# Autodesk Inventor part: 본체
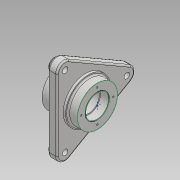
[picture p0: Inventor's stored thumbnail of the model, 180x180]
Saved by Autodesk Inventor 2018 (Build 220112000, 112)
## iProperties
Created: 2023-04
Part Number: 본체
Material: 일반
Document SubType Name: Modeling
Designer: home
Density: 1 g/cm^3
Appearance: 기본값
Author: home
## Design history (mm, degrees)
sketch "스케치1" dims "d0" = 57
  geometry: L1 (-33, 84.87)-(90, 13.856); L2 (90, -13.856)-(-33, -84.87); L3 (-57, -71.014)-(-57, 71.014); A1 r 16 centre (82, 0) between (90, -13.856) and (90, 13.856); A2 r 16 centre (-41, 71.014) between (-33, 84.87) and (-57, 71.014); A3 r 16 centre (-41, -71.014) between (-57, -71.014) and (-33, -84.87); 7 further points
  constraints: 6 end point, 6 point on circle, 6 point on line, 6 tangent, 3 centre point, 2 coincident, 2 equal radius, 1 horizontal alignment, 1 midpoint, 9 other
  dimensions: "d1" = 16 radius of A1 (derived)
extrude "돌출1" new body sketch "스케치1" distance "d2" = 18; taper "d3" = 0 deg
sketch "스케치2"
  geometry: C1 r 45 at (0, 0); 1 further point
  constraints: 1 centre point, 1 coincident
  dimensions: "d4" = 90 diameter of C1
extrude "돌출2" join sketch "스케치2" distance "d5" = 5; taper "d6" = 0 deg
sketch "스케치3"
  geometry: C1 r 45 at (0, 0) reference; C2 r 40 at (0, 0)
  constraints: 1 centre point, 1 coincident
  dimensions: "d7" = 80 diameter of C2
extrude "돌출3" join sketch "스케치3" distance "d8" = 18; taper "d9" = 0 deg
sketch "스케치4"
  geometry: C1 r 40 at (0, 0); 1 further point
  constraints: 1 centre point, 1 coincident
  dimensions: "d10" = 80 diameter of C1
extrude "돌출4" join sketch "스케치4" distance "d11" = 29; taper "d12" = 0 deg
sketch "스케치5"
  geometry: C1 r 40 at (0, 0) reference; 1 further point
  constraints: 1 coincident
hole "구멍1" sketch "스케치5" at (0, 0) diameter "d13" = 42; stored, may be unused: countersink angle "d17" = 90 deg, drill point angle "d19" = 0 deg; dims "d14" = 6, "d15" = 47, "d16" = 17, "d18" = 18
sketch "스케치6"
  geometry: C1 r 40 at (0, 0) reference
hole "구멍2" sketch "스케치6" at (0, 0) diameter "d20" = 42; stored, may be unused: countersink angle "d24" = 90 deg, drill point angle "d26" = 0 deg; dims "d21" = 6, "d22" = 47, "d23" = 17, "d25" = 18
sketch "스케치7"
  geometry: C1 r 23.5 at (0, 0) reference; C2 r 40 at (0, 0) reference; 1 further point
  constraints: 1 coincident
sketch "스케치8"
  geometry: C1 r 40 at (0, 0) reference; C2 r 82 at (0, 0); C3 r 11 at (0, 82); A1 r 16 centre (0, 82) between (13.856, 90) and (-13.856, 90) reference
  constraints: 2 centre point, 2 coincident
  dimensions: "d27" = 164 diameter of C2; "d28" = 22 diameter of C3
extrude "돌출5" join sketch "스케치8" distance "d29" = 4; taper "d30" = 0 deg
sketch "스케치9"
  geometry: C1 r 11 at (0, 0) reference; C2 r 5.5 at (0, 0); 1 further point
  constraints: 1 centre point, 1 coincident
  dimensions: "d31" = 11 diameter of C2
extrude "돌출6" cut sketch "스케치9" extent not by distance; stored distance "d32" = 4; taper "d33" = 0 deg
sketch "스케치10"
  geometry: C1 r 23.5 at (0, 0) reference; 1 further point
  dimensions: "d37" = 32 distance of C1.centre point (0, 32)
hole "구멍3" sketch "스케치10" at (0, 32) diameter "d38" = 3.242; stored, may be unused: countersink angle "d42" = 90 deg, drill point angle "d44" = 118 deg; dims "d39" = 8, "d40" = 4, "d41" = 2, "d43" = 10
sketch "스케치11"
  geometry: C1 r 1.621 at (0, 32) reference; 1 further point
  constraints: 1 coincident
hole "구멍4" sketch "스케치11" at (0, 32) diameter "d48" = 3.242; stored, may be unused: countersink angle "d52" = 90 deg, drill point angle "d54" = 118 deg; dims "d49" = 8, "d50" = 4, "d51" = 2, "d53" = 10
fillet "모깎기1" dims "d58" = 3
fillet "모깎기2" dims "d59" = 3
fillet "모깎기3" dims "d60" = 3
fillet "모깎기4" dims "d61" = 3
chamfer "모따기1" distance "d62" = 1; stored, may be unused: second distance "d63" = 2, angle "d64" = 45 deg
sketch "스케치12"
  geometry: 3 further points
  constraints: 1 horizontal alignment, 2 other
  dimensions: "d65" = 60 vertical distance of point (0, 0) point (0.255, 60)
feature "엠보싱1" sketch "스케치12" dims "d0" = 57, "d1" = 16 (derived), "d7" = 80, "d66" = 0.5, "d67" = 0
node "솔리드1"
pattern_circular "원형 패턴1" dims angle "d35" = 360 deg
pattern_circular "원형 패턴2" dims angle "d46" = 360 deg
pattern_circular "원형 패턴3" dims angle "d56" = 360 deg
